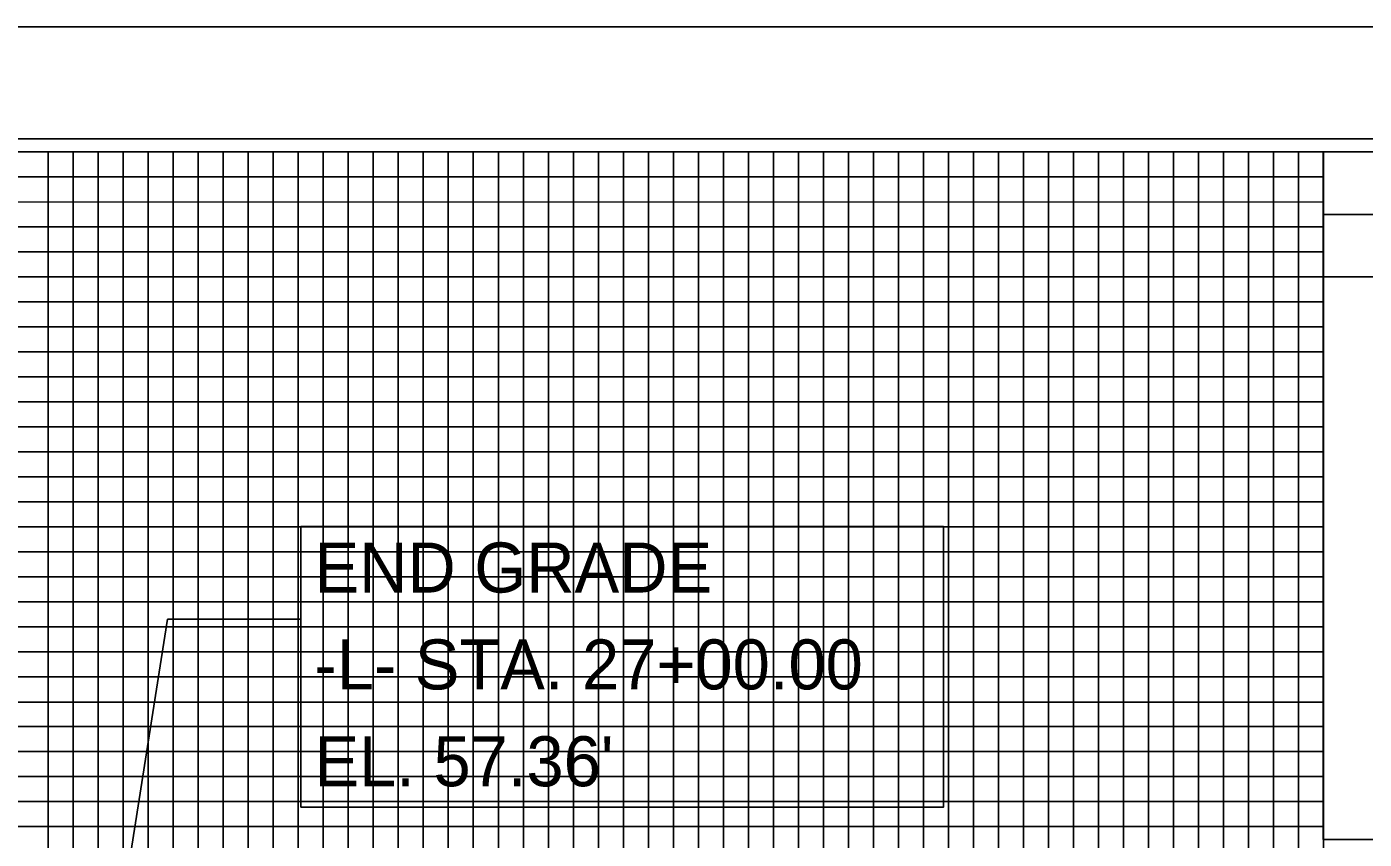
# Model space of a CAD drawing. Extents: x 1019474 to 1021161, y 504129 to 505324.
# Drawn here: x 1020681.9 to 1020949.4, y 505066.8 to 505229.3 of the extents above; entities that cross this region are included whole.
import ezdxf

# ---------------------------------------------------------------- set-up
doc = ezdxf.new("R2010")
doc.units = 0
for name, color, linetype in [('Prop Grid Mask', 7, 'Continuous'), ('Prop Vertical Profile Grade Label', 7, 'Continuous'), ('Sheet Cutting Line CELL', 7, 'Continuous'), ('Sheet DOT Grid CELL', 7, 'Continuous'), ('Sheet Plot Border Inside CELL', 7, 'Continuous'), ('Sheet Plot Border Outside CELL', 7, 'Continuous'), ('Sheet Profile CELL', 7, 'Continuous'), ('Sheet Profile Grid Major CELL', 7, 'Continuous'), ('Sheet Profile Grid Middle CELL', 7, 'Continuous'), ('Sheet Profile Grid Minor CELL', 7, 'Continuous')]:
    doc.layers.add(name, color=color, linetype=linetype)

msp = doc.modelspace()

# ---------------------------------------------------------------- linework, layer by layer
at = {"layer": 'Prop Grid Mask'}
msp.add_lwpolyline([(1020736.75, 505129.3), (1020865.26, 505129.3), (1020865.26, 505073.2), (1020736.75, 505073.2)], close=True, dxfattribs=at)
at = {"layer": 'Prop Vertical Profile Grade Label'}
for p in [(1020691.22, 504991.16), (1020736.75, 505110.82)]:
    msp.add_line(p, (1020710.07, 505110.82), dxfattribs=at)
at = {"layer": 'Sheet Cutting Line CELL'}
msp.add_line((1021158.22, 505229.29), (1019474.22, 505229.29), dxfattribs=at)
at = {"layer": 'Sheet DOT Grid CELL'}
for p, q in [((1020691.22, 504704.29), (1020691.22, 505204.29)), ((1020741.22, 504704.29), (1020741.22, 505204.29)), ((1020791.22, 504704.29), (1020791.22, 505204.29)), ((1020841.22, 504704.29), (1020841.22, 505204.29)), ((1020891.22, 504704.29), (1020891.22, 505204.29)), ((1020941.17, 505154.29), (1019641.22, 505154.29)), ((1020941.17, 505104.29), (1019641.22, 505104.29))]:
    msp.add_line(p, q, dxfattribs=at)
at = {"layer": 'Sheet Plot Border Inside CELL'}
msp.add_lwpolyline([(1019487.22, 504151.74), (1021153.72, 504151.74), (1021153.72, 505206.84), (1019487.22, 505206.84)], close=True, dxfattribs=at)
at = {"layer": 'Sheet Plot Border Outside CELL'}
msp.add_lwpolyline([(1019474.22, 504129.29), (1021158.22, 504129.29), (1021158.22, 505229.29), (1019474.22, 505229.29)], close=True, dxfattribs=at)
at = {"layer": 'Sheet Profile CELL'}
msp.add_line((1020941.17, 505191.74), (1021141.22, 505191.74), dxfattribs=at)
for points in [[(1021141.22, 505204.29), (1019641.22, 505204.29), (1019641.22, 504154.29), (1021141.22, 504154.29)], [(1020941.17, 505204.29), (1021141.22, 505204.29), (1021141.22, 505179.24), (1020941.17, 505179.24)], [(1020941.17, 505179.24), (1021041.22, 505179.24), (1021041.22, 505066.74), (1020941.17, 505066.74)]]:
    msp.add_lwpolyline(points, close=True, dxfattribs=at)
at = {"layer": 'Sheet Profile Grid Major CELL'}
for points in [[(1020641.22, 505204.29), (1020691.22, 505204.29), (1020691.22, 504704.29), (1020741.22, 504704.29), (1020741.22, 505204.29), (1020791.22, 505204.29), (1020791.22, 504704.29), (1020841.22, 504704.29), (1020841.22, 505204.29), (1020891.22, 505204.29), (1020891.22, 504704.29), (1020941.22, 504704.29), (1020941.22, 505204.29), (1020967.52, 505204.29)], [(1019641.22, 505154.29), (1020941.22, 505154.29)], [(1020941.22, 505104.29), (1019641.22, 505104.29), (1019641.22, 505054.29), (1020941.22, 505054.29)]]:
    msp.add_lwpolyline(points, dxfattribs=at)
at = {"layer": 'Sheet Profile Grid Middle CELL'}
msp.add_line((1019641.22, 505179.29), (1020941.17, 505179.29), dxfattribs=at)
for points in [[(1020666.22, 505204.29), (1020716.22, 505204.29), (1020716.22, 504704.29), (1020766.22, 504704.29), (1020766.22, 505204.29), (1020816.22, 505204.29), (1020816.22, 504704.29), (1020866.22, 504704.29), (1020866.22, 505204.29), (1020916.22, 505204.29), (1020916.22, 504704.29), (1020966.22, 504704.29), (1020966.22, 505043.24)], [(1020941.22, 505129.29), (1019641.22, 505129.29), (1019641.22, 505079.29), (1020941.22, 505079.29)]]:
    msp.add_lwpolyline(points, dxfattribs=at)
at = {"layer": 'Sheet Profile Grid Minor CELL'}
for p, q in [((1019691.22, 505199.29), (1020941.22, 505199.29)), ((1020941.22, 505194.29), (1019691.22, 505193.94)), ((1019691.22, 505189.29), (1020941.22, 505189.29)), ((1020941.17, 505069.29), (1019691.22, 505069.29))]:
    msp.add_line(p, q, dxfattribs=at)
for points in [[(1020686.22, 504704.29), (1020686.22, 505204.29), (1020696.22, 505204.29), (1020696.22, 504704.29)], [(1020701.22, 504704.29), (1020701.22, 505204.29), (1020706.22, 505204.29), (1020706.22, 504704.29)], [(1020711.22, 504704.29), (1020711.22, 505204.29), (1020721.22, 505204.29), (1020721.22, 504704.29)], [(1020726.22, 504704.29), (1020726.22, 505204.29), (1020731.22, 505204.29), (1020731.22, 504704.29)], [(1020736.22, 504704.29), (1020736.22, 505204.29), (1020746.22, 505204.29), (1020746.22, 504704.29)], [(1020751.22, 504704.29), (1020751.22, 505204.29), (1020756.22, 505204.29), (1020756.22, 504704.29)], [(1020761.22, 504704.29), (1020761.22, 505204.29), (1020771.22, 505204.29), (1020771.22, 504704.29)], [(1020776.22, 504704.29), (1020776.22, 505204.29), (1020781.22, 505204.29), (1020781.22, 504704.29)], [(1020786.22, 504704.29), (1020786.22, 505204.29), (1020796.22, 505204.29), (1020796.22, 504704.29)], [(1020801.22, 504704.29), (1020801.22, 505204.29), (1020806.22, 505204.29), (1020806.22, 504704.29)], [(1020811.22, 504704.29), (1020811.22, 505204.29), (1020821.22, 505204.29), (1020821.22, 504704.29)], [(1020826.22, 504704.29), (1020826.22, 505204.29), (1020831.22, 505204.29), (1020831.22, 504704.29)], [(1020836.22, 504704.29), (1020836.22, 505204.29), (1020846.22, 505204.29), (1020846.22, 504704.29)], [(1020851.22, 504704.29), (1020851.22, 505204.29), (1020856.22, 505204.29), (1020856.22, 504704.29)], [(1020861.22, 504704.29), (1020861.22, 505204.29), (1020871.22, 505204.29), (1020871.22, 504704.29)], [(1020876.22, 504704.29), (1020876.22, 505204.29), (1020881.22, 505204.29), (1020881.22, 504704.29)], [(1020886.22, 504704.29), (1020886.22, 505204.29), (1020896.22, 505204.29), (1020896.22, 504704.29)], [(1020901.22, 504704.29), (1020901.22, 505204.29), (1020906.22, 505204.29), (1020906.22, 504704.29)], [(1020911.22, 504704.29), (1020911.22, 505204.29), (1020921.22, 505204.29), (1020921.22, 504704.29)], [(1020926.22, 504704.29), (1020926.22, 505204.29), (1020931.22, 505204.29), (1020931.22, 504704.29)], [(1020936.22, 504704.29), (1020936.22, 505204.29), (1020946.22, 505204.29)], [(1020941.22, 505184.29), (1019691.22, 505184.29), (1019691.22, 505174.29), (1020941.22, 505174.29)], [(1020941.17, 505169.29), (1019691.22, 505169.29), (1019691.22, 505164.29), (1020941.22, 505164.29)], [(1020941.22, 505159.29), (1019691.22, 505159.29), (1019691.22, 505149.29), (1020941.22, 505149.29)], [(1020941.22, 505144.29), (1019691.22, 505144.29), (1019691.22, 505139.29), (1020941.22, 505139.29)], [(1020941.22, 505134.29), (1019691.22, 505134.29), (1019691.22, 505124.29), (1020941.22, 505124.29)], [(1020941.22, 505119.29), (1019691.22, 505119.29), (1019691.22, 505114.29), (1020941.22, 505114.29)], [(1020941.22, 505109.29), (1019691.22, 505109.29), (1019691.22, 505099.29), (1020941.22, 505099.29)], [(1020941.22, 505094.19), (1019691.32, 505094.19), (1019691.32, 505089.29), (1020941.22, 505089.29)], [(1020941.22, 505084.29), (1019691.22, 505084.29), (1019691.22, 505074.29), (1020941.22, 505074.29)]]:
    msp.add_lwpolyline(points, dxfattribs=at)

# ---------------------------------------------------------------- texts
at = {"layer": 'Prop Vertical Profile Grade Label'}
for s, p in [('END GRADE', (1020739.46, 505116.12)), ('-L- STA. 27+00.00', (1020739.46, 505096.74)), ("EL. 57.36'", (1020739.46, 505077.37))]:
    msp.add_text(s, height=10, dxfattribs=at).set_placement(p)

doc.saveas('drawing.dxf')
